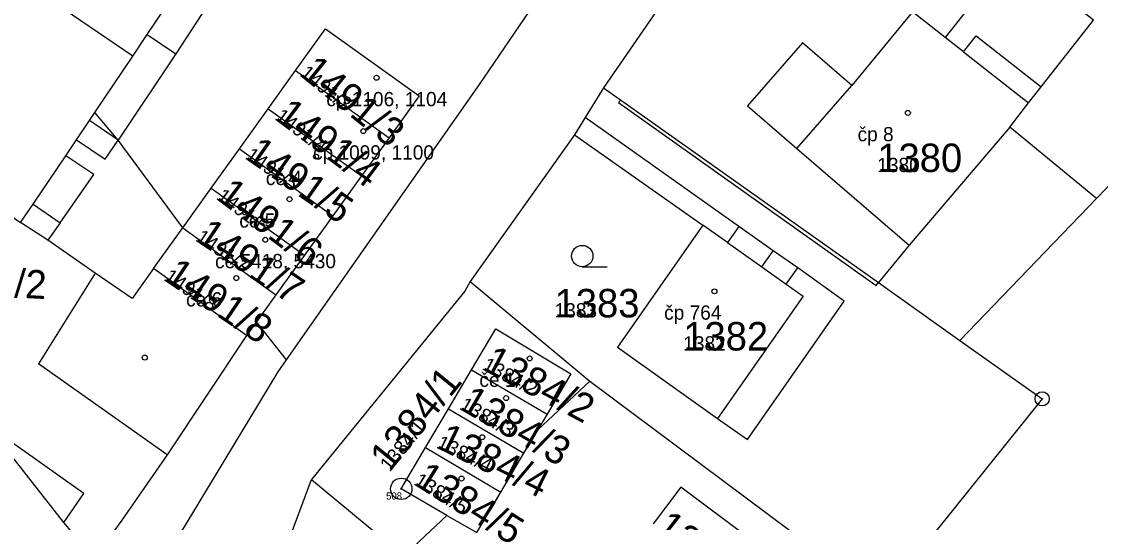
# Model space of a CAD drawing. Extents: x -763628 to -761565, y -976033 to -973833.
# Drawn here: x -762708.9 to -762633.3, y -975520.6 to -975485.4 of the extents above; entities that cross this region are included whole.
import ezdxf

# ---------------------------------------------------------------- set-up
doc = ezdxf.new("R2010")
doc.units = 0
for name, color, linetype in [('KN_cisla parcel 1000', 7, 'Continuous'), ('KN_cisla parcel 500', 7, 'Continuous'), ('KN_cisla popisna 500', 7, 'Continuous'), ('KN_hranice parcel', 7, 'Continuous'), ('KN_vnitrni kresba parcel', 7, 'Continuous'), ('KN_znacky bodu BP', 7, 'Continuous'), ('KN_znacky budov', 7, 'Continuous'), ('KN_znacky kultur', 7, 'Continuous')]:
    doc.layers.add(name, color=color, linetype=linetype)

msp = doc.modelspace()

# ---------------------------------------------------------------- linework, layer by layer
at = {"layer": 'KN_hranice parcel'}
for p, q in [((-762653.13, -975468.34), (-762668.11, -975490.09)), ((-762619.03, -975482.74), (-762633.56, -975497.85)), ((-762691.61, -975491.56), (-762689.69, -975488.87)), ((-762689.69, -975488.87), (-762683.14, -975493.59)), ((-762668.11, -975490.09), (-762669.4, -975492.17)), ((-762702.12, -975493.75), (-762703.77, -975491.82)), ((-762693.63, -975494.36), (-762691.61, -975491.56)), ((-762691.61, -975491.56), (-762685.07, -975496.27)), ((-762669.4, -975492.17), (-762670.14, -975493.38)), ((-762697.61, -975499.91), (-762702.12, -975493.75)), ((-762683.14, -975493.59), (-762685.07, -975496.27)), ((-762670.14, -975493.38), (-762677.46, -975503.67)), ((-762695.61, -975497.12), (-762693.63, -975494.36)), ((-762693.63, -975494.36), (-762687.09, -975499.07)), ((-762685.07, -975496.27), (-762687.09, -975499.07)), ((-762697.61, -975499.91), (-762695.61, -975497.12)), ((-762695.61, -975497.12), (-762689.07, -975501.83)), ((-762633.56, -975497.85), (-762643.13, -975507.8)), ((-762687.09, -975499.07), (-762689.07, -975501.83)), ((-762697.61, -975499.91), (-762691.08, -975504.61)), ((-762689.07, -975501.83), (-762691.08, -975504.61)), ((-762677.46, -975503.67), (-762669.07, -975510.66)), ((-762648.84, -975503.75), (-762643.13, -975507.8)), ((-762691.08, -975504.61), (-762692.43, -975506.49)), ((-762690.33, -975509.16), (-762692.43, -975506.49)), ((-762678.97, -975512.59), (-762677.36, -975509.86)), ((-762677.36, -975509.86), (-762672.07, -975512.98)), ((-762672.74, -975514.1), (-762669.07, -975510.66)), ((-762669.07, -975510.66), (-762648.61, -975525.91)), ((-762680.58, -975515.31), (-762678.97, -975512.59)), ((-762678.97, -975512.59), (-762673.69, -975515.71)), ((-762672.07, -975512.98), (-762672.74, -975514.1)), ((-762673.69, -975515.71), (-762672.74, -975514.1)), ((-762680.58, -975515.31), (-762675.31, -975518.44)), ((-762675.31, -975518.44), (-762673.69, -975515.71)), ((-762682.22, -975523.01), (-762679.09, -975520.07))]:
    msp.add_line(p, q, dxfattribs=at)
for points in [[(-762690.33, -975509.16), (-762676.81, -975489.86), (-762666.29, -975474.41), (-762644.64, -975446.91)], [(-762676.67, -975458.31), (-762686.37, -975472.98), (-762688.9, -975473.99), (-762691.06, -975477.21), (-762696.28, -975484.94), (-762698.09, -975487.71), (-762702.12, -975493.75)], [(-762703.77, -975491.82), (-762701.11, -975487.88), (-762700.09, -975486.35), (-762698.26, -975483.6), (-762693.09, -975475.83), (-762690.96, -975472.63), (-762690.01, -975471.2), (-762686.2, -975465.8), (-762686.35, -975465.7)], [(-762633.56, -975497.85), (-762639.64, -975492.85), (-762638.31, -975491.14), (-762637.43, -975490.01), (-762633.76, -975485.35), (-762639.59, -975480.75), (-762644.15, -975486.56), (-762646.45, -975484.76), (-762650.71, -975489.92), (-762654.17, -975486.94), (-762658.01, -975491.36), (-762654.56, -975494.35), (-762646.69, -975501.12), (-762648.84, -975503.75)], [(-762689.69, -975488.87), (-762687.59, -975485.95), (-762681.04, -975490.66), (-762683.14, -975493.59)], [(-762668.11, -975490.09), (-762666.93, -975490.93), (-762648.84, -975503.75)], [(-762717.57, -975493.6), (-762708.97, -975499.54), (-762708.1, -975498.25), (-762705.81, -975494.85), (-762705.05, -975493.73), (-762704.15, -975492.38), (-762703.77, -975491.82)], [(-762670.14, -975493.38), (-762661.16, -975499.72), (-762667.13, -975508.27), (-762660.12, -975513.28), (-762658.01, -975514.76), (-762651.23, -975505.06), (-762654.49, -975502.72), (-762656.21, -975501.51), (-762658.63, -975499.81), (-762669.4, -975492.17)], [(-762692.43, -975506.49), (-762693.13, -975507.46), (-762699.66, -975502.75), (-762697.61, -975499.91)], [(-762677.46, -975503.67), (-762677.83, -975504.36), (-762688.57, -975517.56)], [(-762677.36, -975509.86), (-762675.66, -975506.98), (-762670.39, -975510.14), (-762672.07, -975512.98)], [(-762643.13, -975507.8), (-762637.36, -975511.9), (-762648.61, -975525.91)], [(-762700.91, -975526.55), (-762690.92, -975510), (-762690.33, -975509.16)], [(-762700.91, -975526.55), (-762703.83, -975523.08), (-762705.94, -975520.56), (-762711.29, -975513.78)], [(-762679.09, -975520.07), (-762682.29, -975518.21), (-762680.58, -975515.31)], [(-762694.38, -975533.14), (-762694.34, -975533.05), (-762688.57, -975517.56)], [(-762688.57, -975517.56), (-762683.93, -975521.4), (-762682.22, -975523.01)], [(-762679.09, -975520.07), (-762676.99, -975521.28), (-762675.31, -975518.44)], [(-762657.86, -975521.71), (-762662.68, -975518.09), (-762664.63, -975520.66)]]:
    msp.add_lwpolyline(points, dxfattribs=at)
at = {"layer": 'KN_vnitrni kresba parcel'}
for p, q in [((-762701.11, -975487.88), (-762709.66, -975482.03)), ((-762700.09, -975486.35), (-762698.09, -975487.71)), ((-762642.87, -975487.57), (-762644.15, -975486.56)), ((-762642.87, -975487.57), (-762641.98, -975486.44)), ((-762641.98, -975486.44), (-762637.43, -975490.01)), ((-762642.87, -975487.57), (-762638.31, -975491.14)), ((-762654.56, -975494.35), (-762650.71, -975489.92)), ((-762666.93, -975490.93), (-762667.07, -975491.13)), ((-762667.07, -975491.13), (-762648.99, -975503.96)), ((-762702.12, -975493.75), (-762704.15, -975492.38)), ((-762639.64, -975492.85), (-762646.69, -975501.12)), ((-762705.05, -975493.73), (-762703.04, -975495.09)), ((-762703.04, -975495.09), (-762702.12, -975493.75)), ((-762703.84, -975496.18), (-762705.81, -975494.85)), ((-762706.19, -975499.55), (-762703.84, -975496.18)), ((-762708.1, -975498.25), (-762706.19, -975499.55)), ((-762707.06, -975500.78), (-762708.97, -975499.54)), ((-762706.19, -975499.55), (-762707.06, -975500.78)), ((-762659.43, -975500.94), (-762661.16, -975499.72)), ((-762658.63, -975499.81), (-762659.43, -975500.94)), ((-762703.75, -975503.09), (-762707.06, -975500.78)), ((-762659.43, -975500.94), (-762657.01, -975502.65)), ((-762657.01, -975502.65), (-762656.21, -975501.51)), ((-762699.66, -975502.75), (-762701.15, -975504.86)), ((-762657.01, -975502.65), (-762655.3, -975503.86)), ((-762655.3, -975503.86), (-762654.49, -975502.72)), ((-762703.75, -975503.09), (-762707.71, -975509.44)), ((-762701.15, -975504.86), (-762703.75, -975503.09)), ((-762655.3, -975503.86), (-762654.12, -975504.69)), ((-762648.99, -975503.96), (-762648.84, -975503.75)), ((-762654.12, -975504.69), (-762660.12, -975513.28)), ((-762693.13, -975507.46), (-762698.69, -975515.83)), ((-762698.69, -975515.83), (-762707.71, -975509.44)), ((-762704.53, -975518.54), (-762711.29, -975513.78)), ((-762698.69, -975515.83), (-762701.88, -975520.41)), ((-762705.94, -975520.56), (-762704.53, -975518.54)), ((-762701.88, -975520.41), (-762703.83, -975523.08))]:
    msp.add_line(p, q, dxfattribs=at)
at = {"layer": 'KN_znacky bodu BP'}
for centre, radius in [((-762637.36, -975511.9), 0.5), ((-762637.36, -975511.9), 0.0303), ((-762682.29, -975518.21), 0.75), ((-762682.29, -975518.21), 0.03)]:
    msp.add_circle(centre, radius, dxfattribs=at)
at = {"layer": 'KN_znacky budov'}
for centre in [(-762684.017, -975489.389), (-762646.777, -975491.849), (-762684.947, -975493.129), (-762688.257, -975494.919), (-762690.117, -975497.899), (-762691.817, -975500.749), (-762693.847, -975503.429), (-762660.337, -975504.359), (-762700.267, -975509.009), (-762673.287, -975509.069), (-762674.937, -975511.849), (-762676.607, -975514.589), (-762678.057, -975517.489)]:
    msp.add_circle(centre, 0.175, dxfattribs=at)
at = {"layer": 'KN_znacky kultur'}
msp.add_line((-762669.603, -975502.64), (-762667.853, -975502.64), dxfattribs=at)
msp.add_circle((-762669.603, -975501.89), 0.75, dxfattribs=at)

# ---------------------------------------------------------------- texts
at = {"layer": 'KN_cisla parcel 1000'}
for s, rotation, p in [('1491/3', 321, (-762689.454, -975489.2)), ('1491/4', 323, (-762691.211, -975492.268)), ('1491/5', 325, (-762693.297, -975495.016)), ('1491/6', 323, (-762695.311, -975497.858)), ('1491/7', 326, (-762696.775, -975500.774)), ('1487/2', 357, (-762715.374, -975504.478)), ('1491/8', 326, (-762698.995, -975503.544)), ('1384/2', 332, (-762676.678, -975509.815)), ('1384/1', 51, (-762683.089, -975517.064)), ('1384/3', 330, (-762678.275, -975512.586)), ('1384/4', 334, (-762679.891, -975515.304)), ('1384/5', 328, (-762681.471, -975517.876)), ('1387/8', 322, (-762664.63, -975521.151))]:
    msp.add_text(s, height=2, rotation=rotation, dxfattribs=at).set_placement(p)
for s, p in [('1380', (-762648.92, -975496)), ('1383', (-762671.54, -975506.19)), ('1382', (-762662.52, -975508.51))]:
    msp.add_text(s, height=2, dxfattribs=at).set_placement(p)
at = {"layer": 'KN_cisla parcel 500'}
for s, rotation, p in [('1491/3', 321, (-762689.454, -975489.2)), ('1491/4', 323, (-762691.211, -975492.268)), ('1491/5', 325, (-762693.297, -975495.016)), ('1491/6', 323, (-762695.311, -975497.858)), ('1491/7', 326, (-762696.775, -975500.774)), ('1491/8', 326, (-762698.995, -975503.544)), ('1384/2', 332, (-762676.678, -975509.815)), ('1384/3', 330, (-762678.275, -975512.586)), ('1384/1', 51, (-762683.089, -975517.064)), ('1384/4', 334, (-762679.891, -975515.304)), ('1384/5', 328, (-762681.471, -975517.876))]:
    msp.add_text(s, height=1, rotation=rotation, dxfattribs=at).set_placement(p)
for s, p in [('1380', (-762648.92, -975496)), ('1383', (-762671.54, -975506.19)), ('1382', (-762662.52, -975508.51))]:
    msp.add_text(s, height=1, dxfattribs=at).set_placement(p)
at = {"layer": 'KN_cisla popisna 500'}
for s, p in [('čp 1106, 1104', (-762687.541, -975491.381)), ('čp 8', (-762650.301, -975493.841)), ('čp 1099, 1100', (-762688.471, -975495.121)), ('če 4', (-762691.781, -975496.911)), ('če 5', (-762693.641, -975499.891)), ('če 5418, 5430', (-762695.341, -975502.741)), ('če 6', (-762697.371, -975505.421)), ('čp 764', (-762663.861, -975506.351)), ('če 1', (-762676.811, -975511.061))]:
    msp.add_text(s, height=1, dxfattribs=at).set_placement(p)
at = {"layer": 'KN_znacky bodu BP'}
msp.add_text('508', height=0.5, dxfattribs=at).set_placement((-762683.351, -975518.96))

doc.saveas('drawing.dxf')
